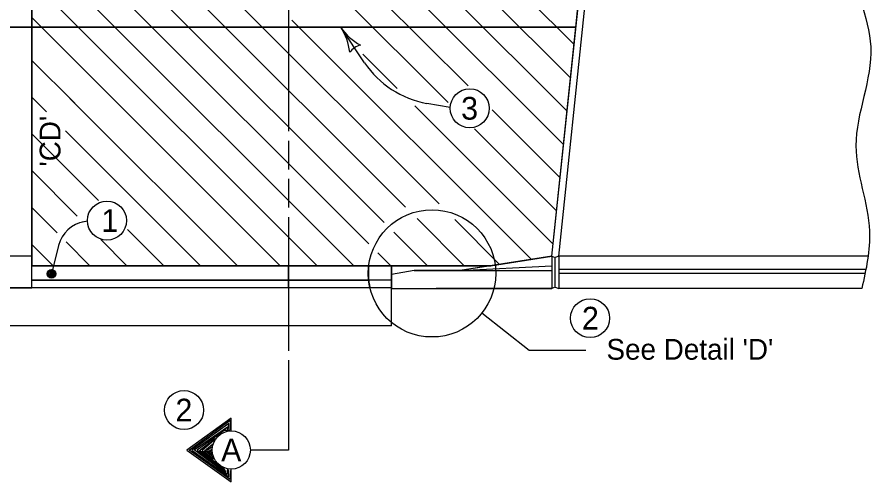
# Model space of a CAD drawing. Extents: x 10045 to 81668, y 6370 to 11018.
# Drawn here: x 11617 to 12310, y 6452 to 6828 of the extents above; entities that cross this region are included whole.
import ezdxf

# ---------------------------------------------------------------- set-up
doc = ezdxf.new("R2010")
doc.units = 0
doc.layers.add('Alignment', color=7, linetype='Continuous')
doc.layers.add('dsnStdLineWork', color=7, linetype='Continuous')

msp = doc.modelspace()

# ---------------------------------------------------------------- linework, layer by layer
at = {"layer": 'Alignment'}
for p, q in [((11628.28, 7263.89), (11628.28, 6819.81)), ((11628.28, 7263.89), (11628.28, 6819.81)), ((12067.52, 6819.81), (12114.2, 7263.88)), ((12067.52, 6819.81), (12114.2, 7263.88)), ((12067.55, 6819.82), (10703.15, 6819.82)), ((12067.55, 6819.82), (10703.15, 6819.82)), ((11628.28, 6819.81), (11628.28, 6819.81)), ((11628.28, 6819.81), (12067.52, 6819.81)), ((11628.28, 6819.81), (11628.28, 6819.81)), ((11628.28, 6819.81), (12067.52, 6819.81)), ((11897, 6791.08), (11877.68, 6819.82)), ((11897, 6791.08), (11877.68, 6819.82)), ((11966.13, 6754.83), (11947.35, 6758.21)), ((11966.13, 6754.83), (11947.35, 6758.21)), ((11649.93, 6643.48), (11644.22, 6620.55)), ((11649.93, 6643.48), (11644.22, 6620.55)), ((11991.68, 6588.98), (12029.71, 6558.85)), ((11991.68, 6588.98), (12029.71, 6558.85)), ((12029.71, 6558.85), (12075.7, 6558.85)), ((12029.71, 6558.85), (12075.7, 6558.85))]:
    msp.add_line(p, q, dxfattribs=at)
for points in [[(11835.61, 6843.69), (11835.61, 6735.75)], [(11835.61, 6843.69), (11835.61, 6735.75)], [(11835.61, 6728.04), (11835.61, 6704.91)], [(11835.61, 6728.04), (11835.61, 6704.91)], [(11835.61, 6697.2), (11835.61, 6674.07)], [(11835.61, 6697.2), (11835.61, 6674.07)], [(11835.61, 6666.36), (11835.61, 6558.43)], [(11835.61, 6666.36), (11835.61, 6558.43)], [(11835.61, 6550.72), (11835.61, 6527.59)], [(11835.61, 6550.72), (11835.61, 6527.59)], [(11835.61, 6530.16), (11835.61, 6478.19), (11804.78, 6478.19)], [(11835.61, 6530.16), (11835.61, 6478.19), (11804.78, 6478.19)]]:
    msp.add_lwpolyline(points, dxfattribs=at)
for centre, radius, start, end in [((11960.98, 6834.09), 77.1, 213.90793, 259.81252), ((11960.98, 6834.09), 77.1, 213.90793, 259.81252), ((11674.87, 6637.27), 25.7, 99.54445, 166.01545), ((11674.87, 6637.27), 25.7, 99.54445, 166.01545)]:
    msp.add_arc(centre, radius, start, end, dxfattribs=at)
at = {"layer": 'dsnStdLineWork'}
for p, q in [((12048.1, 6634.79), (12133.67, 7448.92)), ((12048.1, 6634.79), (12133.67, 7448.92)), ((12053.68, 6634.79), (12139.25, 7448.92)), ((12053.68, 6634.79), (12139.25, 7448.92)), ((11628.28, 6819.81), (11628.28, 7263.89)), ((11628.28, 6819.81), (11628.28, 7263.89)), ((11628.31, 6819.82), (11628.31, 7263.89)), ((11628.31, 6819.82), (11628.31, 7263.89)), ((11628.31, 6609.34), (11628.31, 7112.29)), ((11628.31, 6609.34), (11628.31, 7112.29)), ((12066.07, 6805.74), (11840.25, 7031.56)), ((12066.07, 6805.74), (11840.25, 7031.56)), ((11957.18, 6677.04), (11628.31, 7005.91)), ((11957.18, 6677.04), (11628.31, 7005.91)), ((12063.24, 6778.86), (11839.64, 7002.47)), ((12063.24, 6778.86), (11839.64, 7002.47)), ((12060.42, 6751.99), (11840.91, 6971.5)), ((12060.42, 6751.99), (11840.91, 6971.5)), ((11929.98, 6674.54), (11655.47, 6949.05)), ((11929.98, 6674.54), (11655.47, 6949.05)), ((12057.6, 6725.11), (11839.5, 6943.21)), ((12057.6, 6725.11), (11839.5, 6943.21)), ((11912.72, 6662.1), (11655.47, 6919.35)), ((11912.72, 6662.1), (11655.47, 6919.35)), ((11980.56, 6772.45), (11839.69, 6913.32)), ((11980.56, 6772.45), (11839.69, 6913.32)), ((11900.29, 6644.83), (11638.85, 6906.27)), ((11900.29, 6644.83), (11638.85, 6906.27)), ((11888.35, 6627.08), (11628.31, 6887.12)), ((11888.35, 6627.08), (11628.31, 6887.12)), ((11964.37, 6758.94), (11842.31, 6881)), ((11964.37, 6758.94), (11842.31, 6881)), ((11858.65, 6627.08), (11628.31, 6857.42)), ((11858.65, 6627.08), (11628.31, 6857.42)), ((11705.08, 6750.94), (11628.31, 6827.72)), ((11705.08, 6750.94), (11628.31, 6827.72)), ((12031.7, 6632.22), (11838.27, 6825.65)), ((12031.7, 6632.22), (11838.27, 6825.65)), ((11258.22, 6819.81), (11628.28, 6819.81)), ((11258.22, 6819.81), (11628.28, 6819.81)), ((11258.22, 6819.81), (11628.28, 6819.81)), ((11258.22, 6819.81), (11628.28, 6819.81)), ((11628.28, 6819.81), (11628.28, 6634.78)), ((12067.53, 6819.81), (11628.28, 6819.81)), ((11628.28, 6819.81), (11628.28, 6627.07)), ((11628.28, 6819.81), (11628.28, 6634.78)), ((12067.53, 6819.81), (11628.28, 6819.81)), ((11628.28, 6819.81), (11628.28, 6627.07)), ((12048.08, 6634.78), (12067.53, 6819.81)), ((12048.08, 6634.78), (12067.53, 6819.81)), ((11923.21, 6770.4), (11895.55, 6798.07)), ((11923.21, 6770.4), (11895.55, 6798.07)), ((11662.98, 6758.34), (11628.31, 6793.02)), ((11662.98, 6758.34), (11628.31, 6793.02)), ((11628.44, 6769.28), (11628.31, 6769.28)), ((11628.44, 6769.28), (11628.31, 6769.28)), ((11640.24, 6751.38), (11628.31, 6763.32)), ((11640.24, 6751.38), (11628.31, 6763.32)), ((11794.25, 6627.08), (11659.02, 6762.31)), ((11794.25, 6627.08), (11659.02, 6762.31)), ((11828.95, 6627.08), (11700.8, 6755.23)), ((11828.95, 6627.08), (11700.8, 6755.23)), ((12049.12, 6644.49), (11937.45, 6756.17)), ((12049.12, 6644.49), (11937.45, 6756.17)), ((12054.77, 6698.24), (11999.9, 6753.11)), ((12054.77, 6698.24), (11999.9, 6753.11)), ((11682.24, 6679.69), (11628.31, 6733.62)), ((11682.24, 6679.69), (11628.31, 6733.62)), ((11764.55, 6627.08), (11655.47, 6736.16)), ((11764.55, 6627.08), (11655.47, 6736.16)), ((12051.95, 6671.37), (11985.59, 6737.72)), ((12051.95, 6671.37), (11985.59, 6737.72)), ((11664.98, 6667.25), (11628.31, 6703.92)), ((11664.98, 6667.25), (11628.31, 6703.92)), ((11648.69, 6653.64), (11628.31, 6674.02)), ((11648.69, 6653.64), (11628.31, 6674.02)), ((11673.27, 6663.08), (11669, 6662.33)), ((11673.27, 6663.08), (11669, 6662.33)), ((11977.44, 6627.08), (11939.38, 6665.14)), ((11977.44, 6627.08), (11939.38, 6665.14)), ((12006.01, 6628.21), (11969.8, 6664.42)), ((12006.01, 6628.21), (11969.8, 6664.42)), ((11734.85, 6627.08), (11705.6, 6656.33)), ((11734.85, 6627.08), (11705.6, 6656.33)), ((11705.16, 6627.08), (11684.05, 6648.19)), ((11705.16, 6627.08), (11684.05, 6648.19)), ((11947.74, 6627.08), (11920.51, 6654.31)), ((11947.74, 6627.08), (11920.51, 6654.31)), ((11645.56, 6627.08), (11628.31, 6644.33)), ((11645.56, 6627.08), (11628.31, 6644.33)), ((11675.26, 6627.08), (11655.94, 6646.39)), ((11675.26, 6627.08), (11655.94, 6646.39)), ((11628.28, 6634.78), (11258.22, 6634.78)), ((11628.28, 6634.78), (11258.22, 6634.78)), ((11918.05, 6627.08), (11907.55, 6637.58)), ((11918.05, 6627.08), (11907.55, 6637.58)), ((12048.1, 6634.78), (11974.09, 6623.22)), ((12048.1, 6634.78), (11974.09, 6623.22)), ((11998.75, 6627.07), (12048.08, 6634.78)), ((11998.75, 6627.07), (12048.08, 6634.78)), ((12048.08, 6634.78), (12048.08, 6634.78)), ((12048.08, 6634.78), (12048.08, 6634.78)), ((12048.1, 6634.79), (12048.1, 6608.57)), ((12048.1, 6634.79), (12048.1, 6608.57)), ((12048.1, 6634.78), (12048.1, 6608.57)), ((12048.1, 6634.78), (12048.1, 6608.57)), ((12048.11, 6634.77), (12050.89, 6633.63)), ((12048.11, 6634.77), (12050.89, 6633.63)), ((12053.68, 6634.79), (12050.89, 6633.63)), ((12053.68, 6634.79), (12050.89, 6633.63)), ((12303.51, 6634.79), (12053.68, 6634.79)), ((12053.68, 6634.79), (12053.68, 6608.57)), ((12303.51, 6634.79), (12053.68, 6634.79)), ((12053.68, 6634.79), (12053.68, 6608.57)), ((12050.89, 6609.72), (12050.89, 6633.63)), ((12050.89, 6609.72), (12050.89, 6633.63)), ((11628.28, 6627.07), (11998.75, 6627.07)), ((11628.28, 6627.07), (11998.75, 6627.07)), ((11998.78, 6627.08), (11628.31, 6627.08)), ((11628.31, 6615.51), (11628.31, 6627.08)), ((11998.78, 6627.08), (11628.31, 6627.08)), ((11628.31, 6615.51), (11628.31, 6627.08)), ((11835.61, 6615.51), (11835.61, 6627.08)), ((11835.61, 6627.08), (11835.61, 6615.51)), ((11835.61, 6615.51), (11835.61, 6627.08)), ((11835.61, 6627.08), (11835.61, 6615.51)), ((11918.58, 6620.13), (11918.58, 6627.08)), ((11918.58, 6620.13), (11918.58, 6627.08)), ((11918.58, 6627.08), (11918.58, 6620.13)), ((11918.58, 6620.13), (11918.58, 6627.08)), ((11918.58, 6620.13), (11918.58, 6627.08)), ((11918.58, 6627.08), (11918.58, 6620.13)), ((11937.09, 6623.22), (11918.58, 6620.13)), ((11937.09, 6623.22), (11918.58, 6620.13)), ((11937.09, 6623.22), (11918.58, 6620.13)), ((11937.09, 6623.22), (11918.58, 6620.13)), ((11937.09, 6623.22), (12048.1, 6623.22)), ((11974.09, 6623.22), (11937.09, 6623.22)), ((11937.09, 6623.22), (12048.1, 6623.22)), ((11974.09, 6623.22), (11937.09, 6623.22)), ((11998.78, 6627.08), (11974.09, 6623.22)), ((11998.78, 6627.08), (11974.09, 6623.22)), ((11974.09, 6623.22), (12048.1, 6627.07)), ((11974.09, 6623.22), (12048.1, 6627.07)), ((12301.88, 6623.99), (12053.68, 6623.99)), ((12301.88, 6623.99), (12053.68, 6623.99)), ((12301.4, 6620.91), (12053.68, 6620.91)), ((12301.4, 6620.91), (12053.68, 6620.91)), ((11918.58, 6615.51), (11628.31, 6615.51)), ((11835.61, 6615.51), (11628.31, 6615.51)), ((11628.31, 6615.51), (11835.61, 6615.51)), ((11628.31, 6609.35), (11628.31, 6615.51)), ((11918.58, 6615.51), (11628.31, 6615.51)), ((11835.61, 6615.51), (11628.31, 6615.51)), ((11628.31, 6615.51), (11835.61, 6615.51)), ((11628.31, 6609.35), (11628.31, 6615.51)), ((11900.29, 6615.51), (11835.61, 6615.51)), ((11835.61, 6609.35), (11835.61, 6615.51)), ((11835.61, 6615.51), (11900.29, 6615.51)), ((11835.61, 6615.51), (11835.61, 6609.35)), ((11900.29, 6615.51), (11835.61, 6615.51)), ((11835.61, 6609.35), (11835.61, 6615.51)), ((11835.61, 6615.51), (11900.29, 6615.51)), ((11835.61, 6615.51), (11835.61, 6609.35)), ((11918.58, 6608.57), (11918.58, 6620.13)), ((11918.58, 6620.13), (11918.58, 6620.13)), ((11918.58, 6620.13), (11918.58, 6620.13)), ((11918.58, 6620.13), (11918.58, 6620.13)), ((11918.58, 6620.13), (11918.58, 6609.35)), ((11918.58, 6608.57), (11918.58, 6620.13)), ((11918.58, 6620.13), (11918.58, 6620.13)), ((11918.58, 6620.13), (11918.58, 6620.13)), ((11918.58, 6620.13), (11918.58, 6620.13)), ((11918.58, 6620.13), (11918.58, 6609.35)), ((11628.31, 6609.34), (10703.15, 6609.34)), ((11628.31, 6609.34), (10703.15, 6609.34)), ((11918.58, 6609.35), (11628.31, 6609.35)), ((11835.61, 6609.35), (11628.31, 6609.35)), ((11918.58, 6609.35), (11628.31, 6609.35)), ((11835.61, 6609.35), (11628.31, 6609.35)), ((11901.32, 6609.35), (11835.61, 6609.35)), ((11901.32, 6609.35), (11835.61, 6609.35)), ((11918.58, 6609.35), (11901.32, 6609.35)), ((11918.58, 6609.35), (11901.32, 6609.35)), ((11918.58, 6609.35), (11918.58, 6609.35)), ((11918.58, 6609.35), (11918.58, 6609.35)), ((11918.58, 6609.35), (11918.58, 6609.35)), ((11918.58, 6609.35), (11918.58, 6609.35)), ((11918.58, 6608.57), (12048.1, 6608.57)), ((11918.58, 6578.51), (11918.58, 6608.57)), ((11918.58, 6608.57), (12048.1, 6608.57)), ((11918.58, 6578.51), (11918.58, 6608.57)), ((12048.1, 6608.57), (11954.71, 6608.57)), ((12048.1, 6608.57), (11954.71, 6608.57)), ((12050.89, 6609.72), (12048.11, 6608.58)), ((12050.89, 6609.72), (12048.11, 6608.58)), ((12050.89, 6609.72), (12053.68, 6608.57)), ((12050.89, 6609.72), (12053.68, 6608.57)), ((12298.37, 6608.57), (12053.68, 6608.57)), ((12298.37, 6608.57), (12053.68, 6608.57)), ((11918.58, 6578.51), (11591.3, 6578.51)), ((11918.58, 6578.51), (11591.3, 6578.51))]:
    msp.add_line(p, q, dxfattribs=at)
msp.add_lwpolyline([(11628.28, 6627.07), (11628.28, 6634.78), (11258.25, 6634.78), (11258.25, 6609.34), (11628.31, 6609.34), (11628.31, 6627.07)], close=True, dxfattribs=at)
msp.add_lwpolyline([(11628.28, 6627.07), (11628.28, 6634.78), (11258.25, 6634.78), (11258.25, 6609.34), (11628.31, 6609.34), (11628.31, 6627.07)], close=True, dxfattribs=at)
for points in [[(11628.31, 6627.08), (11645.56, 6627.08), (11645.85, 6627.08), (11675.26, 6627.08), (11705.16, 6627.08), (11734.85, 6627.08), (11764.55, 6627.08), (11794.25, 6627.08), (11828.95, 6627.08), (11835.61, 6627.08)], [(11628.31, 6627.08), (11645.56, 6627.08), (11645.85, 6627.08), (11675.26, 6627.08), (11705.16, 6627.08), (11734.85, 6627.08), (11764.55, 6627.08), (11794.25, 6627.08), (11828.95, 6627.08), (11835.61, 6627.08)], [(11644.5, 6623.85), (11643.29, 6623.3), (11641.4, 6622.72), (11641.03, 6620.8), (11641.29, 6619.12), (11642.5, 6617.57), (11644.29, 6617.73), (11646.19, 6617.99), (11647.1, 6619.5), (11647.27, 6621.09), (11646.15, 6623.17), (11644.77, 6623.35), (11642.87, 6622.86), (11641.32, 6621.66), (11641.37, 6619.86), (11642.58, 6618.42), (11644.28, 6618.25), (11646.17, 6618.62), (11646.46, 6619.69), (11646.84, 6620.97), (11645.95, 6622.54), (11644.58, 6622.5), (11643, 6622.24), (11641.86, 6621.36), (11642.44, 6619.79), (11643.63, 6618.87), (11645.21, 6618.81), (11645.61, 6619.67), (11646.11, 6620.63), (11645.34, 6621.88), (11644.17, 6622.17), (11643.13, 6621.61), (11643.05, 6620.44), (11643.6, 6619.61), (11644.67, 6619.32), (11645.19, 6619.76), (11645.49, 6620.41), (11644.93, 6621.34), (11644.19, 6621.53), (11643.45, 6621.09), (11643.58, 6620.46), (11644.12, 6620.04), (11644.86, 6620.07), (11644.84, 6620.6), (11644.2, 6620.9)], [(11644.5, 6623.85), (11643.29, 6623.3), (11641.4, 6622.72), (11641.03, 6620.8), (11641.29, 6619.12), (11642.5, 6617.57), (11644.29, 6617.73), (11646.19, 6617.99), (11647.1, 6619.5), (11647.27, 6621.09), (11646.15, 6623.17), (11644.77, 6623.35), (11642.87, 6622.86), (11641.32, 6621.66), (11641.37, 6619.86), (11642.58, 6618.42), (11644.28, 6618.25), (11646.17, 6618.62), (11646.46, 6619.69), (11646.84, 6620.97), (11645.95, 6622.54), (11644.58, 6622.5), (11643, 6622.24), (11641.86, 6621.36), (11642.44, 6619.79), (11643.63, 6618.87), (11645.21, 6618.81), (11645.61, 6619.67), (11646.11, 6620.63), (11645.34, 6621.88), (11644.17, 6622.17), (11643.13, 6621.61), (11643.05, 6620.44), (11643.6, 6619.61), (11644.67, 6619.32), (11645.19, 6619.76), (11645.49, 6620.41), (11644.93, 6621.34), (11644.19, 6621.53), (11643.45, 6621.09), (11643.58, 6620.46), (11644.12, 6620.04), (11644.86, 6620.07), (11644.84, 6620.6), (11644.2, 6620.9)], [(11835.61, 6627.08), (11858.65, 6627.08), (11888.35, 6627.08), (11900.37, 6627.08)], [(11835.61, 6627.08), (11858.65, 6627.08), (11888.35, 6627.08), (11900.37, 6627.08)], [(11900.37, 6627.08), (11918.05, 6627.08), (11918.58, 6627.08)], [(11900.37, 6627.08), (11918.05, 6627.08), (11918.58, 6627.08)], [(11918.58, 6627.08), (11947.74, 6627.08), (11977.44, 6627.08), (11998.78, 6627.08)], [(11918.58, 6627.08), (11947.74, 6627.08), (11977.44, 6627.08), (11998.78, 6627.08)], [(11789.36, 6493.61), (11789.36, 6503.89), (11753.38, 6478.19), (11789.36, 6452.49), (11789.36, 6462.77)], [(11789.36, 6493.61), (11789.36, 6503.89), (11753.38, 6478.19), (11789.36, 6452.49), (11789.36, 6462.77)], [(11788.35, 6461.76), (11788.44, 6454.31), (11755.32, 6478.2), (11788.51, 6502.24), (11788.28, 6494.33), (11786.88, 6493.94), (11787.43, 6499.68), (11757.49, 6478.2), (11787.43, 6456.4), (11787.12, 6461.91), (11786.03, 6462.14), (11786.11, 6458.5), (11759.51, 6478.28), (11786.18, 6497.04), (11785.64, 6493.87), (11784.48, 6493.56), (11784.63, 6494.64), (11761.75, 6477.97), (11785.02, 6460.44), (11783.86, 6462.38), (11763.77, 6477.81), (11776.1, 6487.58), (11775.33, 6485.8), (11765.87, 6477.73), (11775.02, 6470.75), (11774.16, 6472.62), (11767.8, 6477.5), (11774.16, 6483.01), (11773.54, 6480.61), (11769.43, 6477.42), (11773.62, 6474.17), (11773.39, 6475.87), (11770.99, 6477.35), (11773.31, 6478.74), (11773.16, 6477.27), (11772.38, 6477.35)], [(11788.35, 6461.76), (11788.44, 6454.31), (11755.32, 6478.2), (11788.51, 6502.24), (11788.28, 6494.33), (11786.88, 6493.94), (11787.43, 6499.68), (11757.49, 6478.2), (11787.43, 6456.4), (11787.12, 6461.91), (11786.03, 6462.14), (11786.11, 6458.5), (11759.51, 6478.28), (11786.18, 6497.04), (11785.64, 6493.87), (11784.48, 6493.56), (11784.63, 6494.64), (11761.75, 6477.97), (11785.02, 6460.44), (11783.86, 6462.38), (11763.77, 6477.81), (11776.1, 6487.58), (11775.33, 6485.8), (11765.87, 6477.73), (11775.02, 6470.75), (11774.16, 6472.62), (11767.8, 6477.5), (11774.16, 6483.01), (11773.54, 6480.61), (11769.43, 6477.42), (11773.62, 6474.17), (11773.39, 6475.87), (11770.99, 6477.35), (11773.31, 6478.74), (11773.16, 6477.27), (11772.38, 6477.35)]]:
    msp.add_lwpolyline(points, dxfattribs=at)
for centre, radius in [((11981.87, 6754.31), 15.75), ((11981.87, 6754.31), 15.75), ((11689.01, 6663.58), 15.75), ((11689.01, 6663.58), 15.75), ((11951.4, 6620.91), 51.4), ((11951.4, 6620.91), 51.4), ((11644.22, 6620.55), 3.6), ((11644.22, 6620.55), 3.6), ((11644.22, 6620.55), 3.6), ((11644.22, 6620.55), 3.6), ((12079.04, 6584.73), 15.75), ((12079.04, 6584.73), 15.75), ((11751.23, 6510.45), 15.75), ((11751.23, 6510.45), 15.75), ((11789.36, 6478.19), 15.42), ((11789.36, 6478.19), 15.42)]:
    msp.add_circle(centre, radius, dxfattribs=at)
for centre, radius, start, end in [((11840.84, 6795.05), 44.39, 5.8374, 33.90989), ((11914.52, 6844.58), 44.39, 213.90989, 241.98238), ((11840.84, 6795.05), 44.39, 5.8374, 33.90989), ((11914.52, 6844.58), 44.39, 213.90989, 241.98238), ((11840.84, 6795.05), 44.39, 5.8374, 33.90989), ((11914.52, 6844.58), 44.39, 213.90989, 241.98238), ((11840.84, 6795.05), 44.39, 5.8374, 33.90989), ((11914.52, 6844.58), 44.39, 213.90989, 241.98238), ((11898.44, 6788.93), 17.14, 106.17654, 141.64324), ((11898.44, 6788.93), 17.14, 106.17654, 141.64324), ((11898.44, 6788.93), 17.14, 106.17654, 141.64324), ((11898.44, 6788.93), 17.14, 106.17654, 141.64324), ((11951.4, 6620.91), 51.4, 173.10905, 193.00119), ((11951.4, 6620.91), 51.4, 173.10905, 186.02552), ((11951.4, 6620.91), 51.4, 173.10905, 193.00119), ((11951.4, 6620.91), 51.4, 173.10905, 186.02552), ((11951.4, 6620.91), 51.4, 186.02552, 193.00119), ((11951.4, 6620.91), 51.4, 186.02552, 193.00119)]:
    msp.add_arc(centre, radius, start, end, dxfattribs=at)
msp.add_spline([(12298.56, 7475.12), (12302.98, 7447.4), (12293.82, 7398.34), (12303.63, 7342.1), (12294.47, 7281.93), (12303.63, 7234.84), (12293.82, 7175.97), (12302.98, 7140.66), (12291.63, 7031.41), (12307.6, 6960.54), (12290.64, 6877.7), (12305.61, 6803.84), (12293.63, 6723.98), (12304.61, 6655.11), (12298.39, 6608.62)], degree=3, dxfattribs=at)
msp.add_spline([(12298.56, 7475.12), (12302.98, 7447.4), (12293.82, 7398.34), (12303.63, 7342.1), (12294.47, 7281.93), (12303.63, 7234.84), (12293.82, 7175.97), (12302.98, 7140.66), (12291.63, 7031.41), (12307.6, 6960.54), (12290.64, 6877.7), (12305.61, 6803.84), (12293.63, 6723.98), (12304.61, 6655.11), (12298.39, 6608.62)], degree=3, dxfattribs=at)

# ---------------------------------------------------------------- texts
at = {"layer": 'Alignment'}
for s, height, p in [('3', 18.37, (11974.93, 6745.12)), ('3', 18.37, (11974.93, 6745.12)), ('1', 18.37, (11684.4, 6654.4)), ('1', 18.37, (11684.4, 6654.4)), ('2', 18.37, (12072.45, 6575.54)), ('2', 18.37, (12072.45, 6575.54)), ("See Detail 'D'", 16.8, (12092.24, 6551.16)), ("See Detail 'D'", 16.8, (12092.24, 6551.16)), ('2', 18.37, (11744.3, 6501.26)), ('2', 18.37, (11744.3, 6501.26)), ('A', 18.37, (11781.16, 6469)), ('A', 18.37, (11781.16, 6469))]:
    msp.add_text(s, height=height, dxfattribs=at).set_placement(p)
msp.add_text("'CD'", height=16.8, rotation=90, dxfattribs=at).set_placement((11651.47, 6707.22))
msp.add_text("'CD'", height=16.8, rotation=90, dxfattribs=at).set_placement((11651.47, 6707.22))

doc.saveas('drawing.dxf')
